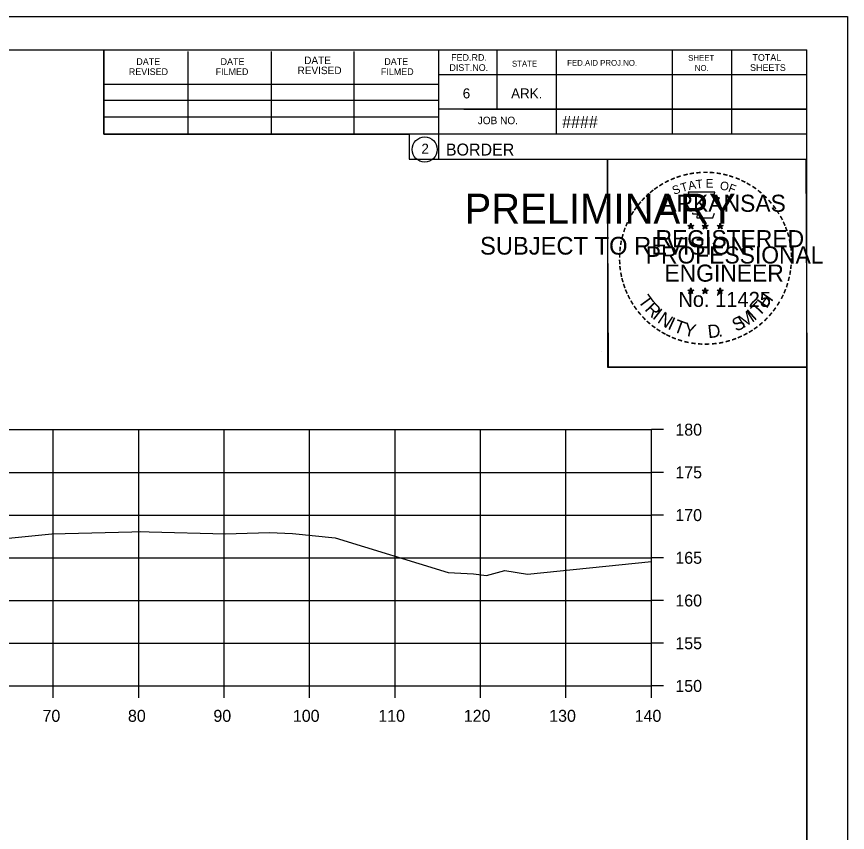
# Model space of a CAD drawing. Extents: x 1368503 to 1373085, y 379840 to 381833.
# Drawn here: x 1372987.8 to 1373085, y 380932.8 to 381028.3 of the extents above; entities that cross this region are included whole.
import ezdxf

# ---------------------------------------------------------------- set-up
doc = ezdxf.new("R2010")
doc.units = 0
for name, color, linetype in [('S_BRIDGE', 7, 'Continuous'), ('S_EDGE_PAVEMENT', 7, 'Continuous'), ('S_LANDSCAPING', 7, 'Continuous'), ('S_MISC_BOUNDARY', 7, 'Continuous'), ('S_MISC_BOUNDARY_ANNOT', 7, 'Continuous'), ('S_PHOTO_CENTERS', 7, 'Continuous'), ('S_PHOTO_NOTES', 7, 'Continuous'), ('S_TRAILS', 7, 'Continuous')]:
    doc.layers.add(name, color=color, linetype=linetype)

msp = doc.modelspace()

# ---------------------------------------------------------------- linework, layer by layer
at = {"layer": 'S_BRIDGE'}
for p, q in [((1372764.081, 381024.423), (1373080.261, 381024.423)), ((1372998.001, 381014.543), (1372998.001, 381024.423)), ((1373037.161, 381024.423), (1373037.161, 381011.623)), ((1373044.001, 381024.423), (1373044.001, 381017.483)), ((1373050.941, 381024.423), (1373050.941, 381014.543)), ((1373064.521, 381024.423), (1373064.521, 381014.543)), ((1373071.461, 381024.423), (1373071.461, 381014.543)), ((1373080.261, 380818.963), (1373080.261, 381024.423)), ((1373007.861, 381014.543), (1373007.861, 381024.223)), ((1373017.621, 381014.543), (1373017.621, 381024.223)), ((1373027.301, 381014.543), (1373027.301, 381024.223)), ((1373080.261, 381021.483), (1373037.161, 381021.483)), ((1373080.261, 381021.503), (1373080.261, 381021.503)), ((1372998.001, 381020.403), (1373037.161, 381020.403)), ((1372998.001, 381018.543), (1373037.161, 381018.543)), ((1372998.001, 381014.543), (1372998.001, 381016.603)), ((1372998.001, 381016.603), (1373037.161, 381016.603)), ((1373080.261, 381017.483), (1373037.161, 381017.483)), ((1373040.121, 381017.483), (1373080.261, 381017.483)), ((1373080.261, 381014.543), (1372998.001, 381014.543)), ((1373037.161, 381011.623), (1373080.261, 381011.623))]:
    msp.add_line(p, q, dxfattribs=at)
msp.add_circle((1373035.548, 381012.759), 1.467, dxfattribs=at)
at = {"layer": 'S_EDGE_PAVEMENT'}
for p, q in [((1373062.081, 380949.963), (1373062.081, 380979.963)), ((1373063.481, 380979.963), (1373062.081, 380979.963)), ((1373063.481, 380974.963), (1373062.081, 380974.963)), ((1373063.481, 380969.963), (1373062.081, 380969.963)), ((1373063.481, 380964.963), (1373062.081, 380964.963)), ((1373063.481, 380959.963), (1373062.081, 380959.963)), ((1373063.481, 380954.963), (1373062.081, 380954.963)), ((1372782.081, 380949.963), (1373062.081, 380949.963)), ((1372992.081, 380948.563), (1372992.081, 380949.963)), ((1373002.081, 380948.563), (1373002.081, 380949.963)), ((1373012.081, 380948.563), (1373012.081, 380949.963)), ((1373022.081, 380948.563), (1373022.081, 380949.963)), ((1373032.081, 380948.563), (1373032.081, 380949.963)), ((1373042.081, 380948.563), (1373042.081, 380949.963)), ((1373052.081, 380948.563), (1373052.081, 380949.963)), ((1373062.081, 380948.563), (1373062.081, 380949.963)), ((1373063.481, 380949.963), (1373062.081, 380949.963))]:
    msp.add_line(p, q, dxfattribs=at)
at = {"layer": 'S_LANDSCAPING'}
for p, q in [((1373066.695, 381004.132), (1373066.654, 381003.88)), ((1373066.695, 381003.767), (1373066.695, 381004.132)), ((1373066.695, 381004.132), (1373066.744, 381003.882)), ((1373068.365, 381004.132), (1373068.324, 381003.88)), ((1373068.365, 381003.767), (1373068.365, 381004.132)), ((1373068.365, 381004.132), (1373068.414, 381003.882)), ((1373070.129, 381004.12), (1373070.088, 381003.868)), ((1373070.129, 381003.755), (1373070.129, 381004.12)), ((1373070.129, 381004.12), (1373070.178, 381003.87)), ((1373066.346, 381003.878), (1373066.695, 381003.767)), ((1373066.346, 381003.878), (1373066.599, 381003.833)), ((1373066.346, 381003.878), (1373066.583, 381003.756)), ((1373066.479, 381003.47), (1373066.695, 381003.767)), ((1373066.479, 381003.47), (1373066.605, 381003.714)), ((1373066.479, 381003.47), (1373066.693, 381003.687)), ((1373066.908, 381003.47), (1373066.693, 381003.684)), ((1373067.042, 381003.878), (1373066.695, 381003.767)), ((1373066.908, 381003.47), (1373066.695, 381003.767)), ((1373067.042, 381003.878), (1373066.756, 381003.829)), ((1373066.908, 381003.47), (1373066.771, 381003.761)), ((1373067.042, 381003.878), (1373066.838, 381003.776)), ((1373068.016, 381003.878), (1373068.365, 381003.767)), ((1373068.016, 381003.878), (1373068.269, 381003.833)), ((1373068.016, 381003.878), (1373068.253, 381003.756)), ((1373068.149, 381003.47), (1373068.365, 381003.767)), ((1373068.149, 381003.47), (1373068.275, 381003.714)), ((1373068.149, 381003.47), (1373068.363, 381003.687)), ((1373068.578, 381003.47), (1373068.363, 381003.684)), ((1373068.712, 381003.878), (1373068.365, 381003.767)), ((1373068.578, 381003.47), (1373068.365, 381003.767)), ((1373068.712, 381003.878), (1373068.426, 381003.829)), ((1373068.578, 381003.47), (1373068.441, 381003.761)), ((1373068.712, 381003.878), (1373068.508, 381003.776)), ((1373069.78, 381003.866), (1373070.129, 381003.755)), ((1373069.78, 381003.866), (1373070.033, 381003.821)), ((1373069.78, 381003.866), (1373070.017, 381003.744)), ((1373069.913, 381003.458), (1373070.129, 381003.755)), ((1373069.913, 381003.458), (1373070.039, 381003.702)), ((1373069.913, 381003.458), (1373070.127, 381003.675)), ((1373070.342, 381003.458), (1373070.127, 381003.672)), ((1373070.476, 381003.866), (1373070.129, 381003.755)), ((1373070.342, 381003.458), (1373070.129, 381003.755)), ((1373070.476, 381003.866), (1373070.19, 381003.817)), ((1373070.342, 381003.458), (1373070.205, 381003.749)), ((1373070.476, 381003.866), (1373070.272, 381003.764)), ((1373066.342, 380996.305), (1373066.691, 380996.194)), ((1373066.342, 380996.305), (1373066.595, 380996.26)), ((1373066.342, 380996.305), (1373066.579, 380996.183)), ((1373066.475, 380995.897), (1373066.691, 380996.194)), ((1373066.475, 380995.897), (1373066.601, 380996.141)), ((1373066.691, 380996.559), (1373066.65, 380996.307)), ((1373066.691, 380996.194), (1373066.691, 380996.559)), ((1373066.691, 380996.559), (1373066.74, 380996.309)), ((1373067.038, 380996.305), (1373066.691, 380996.194)), ((1373066.904, 380995.897), (1373066.691, 380996.194)), ((1373067.038, 380996.305), (1373066.752, 380996.256)), ((1373066.904, 380995.897), (1373066.767, 380996.188)), ((1373067.038, 380996.305), (1373066.834, 380996.203)), ((1373068.011, 380996.305), (1373068.36, 380996.194)), ((1373068.011, 380996.305), (1373068.264, 380996.26)), ((1373068.011, 380996.305), (1373068.248, 380996.183)), ((1373068.144, 380995.897), (1373068.36, 380996.194)), ((1373068.144, 380995.897), (1373068.27, 380996.141)), ((1373068.36, 380996.559), (1373068.319, 380996.307)), ((1373068.36, 380996.194), (1373068.36, 380996.559)), ((1373068.36, 380996.559), (1373068.409, 380996.309)), ((1373068.707, 380996.305), (1373068.36, 380996.194)), ((1373068.573, 380995.897), (1373068.36, 380996.194)), ((1373068.707, 380996.305), (1373068.421, 380996.256)), ((1373068.573, 380995.897), (1373068.436, 380996.188)), ((1373068.707, 380996.305), (1373068.503, 380996.203)), ((1373069.778, 380996.295), (1373070.127, 380996.184)), ((1373069.778, 380996.295), (1373070.031, 380996.25)), ((1373069.778, 380996.295), (1373070.015, 380996.173)), ((1373069.911, 380995.887), (1373070.127, 380996.184)), ((1373069.911, 380995.887), (1373070.037, 380996.131)), ((1373070.127, 380996.549), (1373070.086, 380996.297)), ((1373070.127, 380996.184), (1373070.127, 380996.549)), ((1373070.127, 380996.549), (1373070.176, 380996.299)), ((1373070.474, 380996.295), (1373070.127, 380996.184)), ((1373070.34, 380995.887), (1373070.127, 380996.184)), ((1373070.474, 380996.295), (1373070.188, 380996.246)), ((1373070.34, 380995.887), (1373070.203, 380996.178)), ((1373070.474, 380996.295), (1373070.27, 380996.193)), ((1373066.475, 380995.897), (1373066.689, 380996.114)), ((1373066.904, 380995.897), (1373066.689, 380996.111)), ((1373068.144, 380995.897), (1373068.358, 380996.114)), ((1373068.573, 380995.897), (1373068.358, 380996.111)), ((1373069.911, 380995.887), (1373070.125, 380996.104)), ((1373070.34, 380995.887), (1373070.125, 380996.101))]:
    msp.add_line(p, q, dxfattribs=at)
for points in [[(1373066.387, 381007.756), (1373066.656, 381006.929)], [(1373069.898, 381006.834), (1373070.04, 381007.118), (1373069.355, 381007.094), (1373069.503, 381007.756), (1373066.387, 381007.756)], [(1373066.879, 381005.333), (1373066.879, 381005.246), (1373067.442, 381005.227), (1373067.388, 381004.754), (1373069.258, 381004.754), (1373069.459, 381005.29)], [(1373066.695, 381004.132), (1373066.908, 381003.47), (1373066.346, 381003.878), (1373067.042, 381003.878), (1373066.479, 381003.47), (1373066.695, 381004.132)], [(1373068.365, 381004.132), (1373068.578, 381003.47), (1373068.016, 381003.878), (1373068.712, 381003.878), (1373068.149, 381003.47), (1373068.365, 381004.132)], [(1373070.129, 381004.12), (1373070.342, 381003.458), (1373069.78, 381003.866), (1373070.476, 381003.866), (1373069.913, 381003.458), (1373070.129, 381004.12)], [(1373066.691, 380996.559), (1373066.904, 380995.897), (1373066.342, 380996.305), (1373067.038, 380996.305), (1373066.475, 380995.897), (1373066.691, 380996.559)], [(1373068.36, 380996.559), (1373068.573, 380995.897), (1373068.011, 380996.305), (1373068.707, 380996.305), (1373068.144, 380995.897), (1373068.36, 380996.559)], [(1373070.127, 380996.549), (1373070.34, 380995.887), (1373069.778, 380996.295), (1373070.474, 380996.295), (1373069.911, 380995.887), (1373070.127, 380996.549)]]:
    msp.add_lwpolyline(points, dxfattribs=at)
for centre, radius in [((1373066.694, 381003.766), 0.172), ((1373066.694, 381003.766), 0.145), ((1373068.364, 381003.766), 0.172), ((1373068.364, 381003.766), 0.145), ((1373070.128, 381003.754), 0.172), ((1373066.694, 381003.766), 0.116), ((1373066.694, 381003.766), 0.0991), ((1373066.694, 381003.766), 0.0747), ((1373066.694, 381003.766), 0.0495), ((1373066.694, 381003.766), 0.0296), ((1373068.364, 381003.766), 0.116), ((1373068.364, 381003.766), 0.0991), ((1373068.364, 381003.766), 0.0747), ((1373068.364, 381003.766), 0.0495), ((1373068.364, 381003.766), 0.0296), ((1373070.128, 381003.754), 0.145), ((1373070.128, 381003.754), 0.116), ((1373070.128, 381003.754), 0.0991), ((1373070.128, 381003.754), 0.0747), ((1373070.128, 381003.754), 0.0495), ((1373070.128, 381003.754), 0.0296), ((1373066.69, 380996.193), 0.172), ((1373066.69, 380996.193), 0.145), ((1373066.69, 380996.193), 0.116), ((1373066.69, 380996.193), 0.0991), ((1373066.69, 380996.193), 0.0747), ((1373066.69, 380996.193), 0.0495), ((1373066.69, 380996.193), 0.0296), ((1373068.359, 380996.193), 0.172), ((1373068.359, 380996.193), 0.145), ((1373068.359, 380996.193), 0.116), ((1373068.359, 380996.193), 0.0991), ((1373068.359, 380996.193), 0.0747), ((1373068.359, 380996.193), 0.0495), ((1373068.359, 380996.193), 0.0296), ((1373070.126, 380996.183), 0.172), ((1373070.126, 380996.183), 0.145), ((1373070.126, 380996.183), 0.116), ((1373070.126, 380996.183), 0.0991), ((1373070.126, 380996.183), 0.0747), ((1373070.126, 380996.183), 0.0495), ((1373070.126, 380996.183), 0.0296)]:
    msp.add_circle(centre, radius, dxfattribs=at)
at = {"layer": 'S_MISC_BOUNDARY'}
msp.add_lwpolyline([(1372874.557, 380962.386), (1372926.18, 380962.188), (1372929.874, 380962.189), (1372955.958, 380961.956), (1372968.41, 380961.854), (1372969.229, 380962.173), (1372972.62, 380963.246), (1372983.457, 380966.906), (1372984.077, 380966.974), (1372991.899, 380967.757), (1373001.26, 380968.002), (1373002.326, 380968.027), (1373003.309, 380968.002), (1373012.255, 380967.781), (1373013.501, 380967.805), (1373017.378, 380967.906), (1373020.086, 380967.799), (1373025.072, 380967.294), (1373038.307, 380963.227), (1373041.268, 380963.094), (1373042.787, 380962.899), (1373044.934, 380963.461), (1373047.57, 380963.065), (1373062.081, 380964.517)], dxfattribs=at)
at = {"layer": 'S_PHOTO_CENTERS'}
for p, q in [((1372782.081, 380979.963), (1373062.081, 380979.963)), ((1372782.081, 380979.963), (1373062.081, 380979.963)), ((1372992.081, 380949.963), (1372992.081, 380979.963)), ((1372992.081, 380949.963), (1372992.081, 380979.963)), ((1373002.081, 380949.963), (1373002.081, 380979.963)), ((1373002.081, 380949.963), (1373002.081, 380979.963)), ((1373012.081, 380949.963), (1373012.081, 380979.963)), ((1373012.081, 380949.963), (1373012.081, 380979.963)), ((1373022.081, 380949.963), (1373022.081, 380979.963)), ((1373022.081, 380949.963), (1373022.081, 380979.963)), ((1373032.081, 380949.963), (1373032.081, 380979.963)), ((1373032.081, 380949.963), (1373032.081, 380979.963)), ((1373042.081, 380949.963), (1373042.081, 380979.963)), ((1373042.081, 380949.963), (1373042.081, 380979.963)), ((1373052.081, 380949.963), (1373052.081, 380979.963)), ((1373052.081, 380949.963), (1373052.081, 380979.963)), ((1373062.081, 380949.963), (1373062.081, 380979.963)), ((1373062.081, 380949.963), (1373062.081, 380979.963)), ((1372782.081, 380974.963), (1373062.081, 380974.963)), ((1372782.081, 380974.963), (1373062.081, 380974.963)), ((1372782.081, 380969.963), (1373062.081, 380969.963)), ((1372782.081, 380969.963), (1373062.081, 380969.963)), ((1372782.081, 380964.963), (1373062.081, 380964.963)), ((1372782.081, 380964.963), (1373062.081, 380964.963)), ((1372782.081, 380959.963), (1373062.081, 380959.963)), ((1372782.081, 380959.963), (1373062.081, 380959.963)), ((1372782.081, 380954.963), (1373062.081, 380954.963)), ((1372782.081, 380954.963), (1373062.081, 380954.963)), ((1372782.081, 380949.963), (1373062.081, 380949.963)), ((1372782.081, 380949.963), (1373062.081, 380949.963))]:
    msp.add_line(p, q, dxfattribs=at)
at = {"layer": 'S_PHOTO_NOTES'}
for p, q in [((1372751.681, 381028.318), (1373085.014, 381028.318)), ((1373056.296, 380989.168), (1373056.296, 380989.168))]:
    msp.add_line(p, q, dxfattribs=at)
for points in [[(1372751.674, 381028.318), (1373085.014, 381028.318), (1373085.014, 380814.98), (1372751.674, 380814.98)], [(1372998.001, 381024.423), (1372998.001, 381014.543), (1373033.733, 381014.543), (1373033.733, 381011.623), (1373056.933, 381011.623), (1373056.933, 380987.291), (1373080.261, 380987.291), (1373080.261, 380818.963), (1372764.081, 380818.963), (1372764.081, 381024.423)], [(1373056.933, 381011.623), (1373080.141, 381011.623), (1373080.261, 380987.291), (1373057.054, 380987.291)]]:
    msp.add_lwpolyline(points, close=True, dxfattribs=at)

# ---------------------------------------------------------------- texts
at = {"layer": 'S_BRIDGE'}
for s, height, p in [('DATE', 0.7819, (1373001.801, 381022.663)), ('DATE', 0.7819, (1373011.661, 381022.663)), ('DATE', 0.8792, (1373021.441, 381022.763)), ('DATE', 0.7819, (1373030.821, 381022.663)), ('FED.RD.', 0.7819, (1373038.641, 381023.143)), ('SHEET', 0.684, (1373066.381, 381023.143)), ('TOTAL', 0.7819, (1373073.901, 381023.143)), ('REVISED', 0.8792, (1373020.661, 381021.583)), ('DIST.NO.', 0.7819, (1373038.441, 381021.963)), ('STATE', 0.684, (1373045.761, 381022.463)), ('FED.AID PROJ.NO.', 0.684, (1373052.221, 381022.563)), ('NO.', 0.684, (1373067.161, 381021.963)), ('SHEETS', 0.7819, (1373073.621, 381021.963)), ('REVISED', 0.7819, (1373000.921, 381021.483)), ('FILMED', 0.7819, (1373011.081, 381021.483)), ('FILMED', 0.7819, (1373030.421, 381021.483)), ('6', 1.172, (1373040.001, 381018.743)), ('ARK.', 1.1723, (1373045.661, 381018.743)), ('JOB NO.', 0.8792, (1373041.761, 381015.723)), ('####', 1.4, (1373051.637, 381015.283)), ('2', 1.172, (1373035.165, 381012.273)), ('BORDER', 1.4, (1373038.025, 381012.053))]:
    msp.add_text(s, height=height, rotation=360, dxfattribs=at).set_placement(p)
at = {"layer": 'S_LANDSCAPING'}
for s, height, rotation, p in [('-', 1.6, 19.17608, (1373065.135, 381008.883)), ('-', 1.6, 13.63015, (1373065.885, 381009.124)), ('-', 1.6, 10.21935, (1373066.563, 381009.286)), ('-', 1.6, 5.89682, (1373067.292, 381009.396)), ('-', 1.6, 0.18623, (1373068.064, 381009.468)), ('-', 1.6, 357.74304, (1373068.787, 381009.455)), ('-', 1.6, 352.16172, (1373069.531, 381009.399)), ('-', 1.6, 347.20489, (1373070.25, 381009.285)), ('-', 1.6, 342.3362, (1373070.885, 381009.13)), ('-', 1.6, 34.06357, (1373063.271, 381007.927)), ('-', 1.6, 28.79182, (1373063.868, 381008.297)), ('-', 1.6, 24.30721, (1373064.501, 381008.614)), ('T', 1, 16.4036, (1373065.656, 381007.765)), ('A', 1, 11.21318, (1373066.482, 381008.016)), ('T', 1, 6.02276, (1373067.331, 381008.182)), ('E', 1, 0.83234, (1373068.436, 381008.292)), ('O', 1, 350.4515, (1373070.04, 381008.082)), ('-', 1.6, 337.85509, (1373071.62, 381008.907)), ('-', 1.6, 334.12109, (1373072.251, 381008.636)), ('-', 1.6, 329.64089, (1373072.83, 381008.353)), ('-', 1.6, 38.95066, (1373062.217, 381007.154)), ('-', 1.6, 36.23174, (1373062.693, 381007.532)), ('S', 1, 21.59401, (1373064.742, 381007.434)), ('F', 1, 340.07066, (1373070.994, 381007.854)), ('-', 1.6, 325.86266, (1373073.473, 381007.992)), ('-', 1.6, 320.52971, (1373074.083, 381007.566)), ('-', 1.6, 48.42305, (1373061.336, 381006.259)), ('-', 1.6, 42.96224, (1373061.784, 381006.737)), ('ARKANSAS', 2, 360, (1373063.24, 381005.468)), ('-', 1.6, 315.57859, (1373074.682, 381007.078)), ('-', 1.6, 309.87973, (1373075.251, 381006.528)), ('-', 1.6, 54.23247, (1373060.52, 381005.206)), ('-', 1.6, 50.61417, (1373060.933, 381005.773)), ('-', 1.6, 306.65218, (1373075.776, 381005.926)), ('-', 1.6, 62.87135, (1373059.882, 381004.065)), ('-', 1.6, 58.07063, (1373060.195, 381004.679)), ('-', 1.4, 303.67529, (1373076.262, 381005.358)), ('-', 1.6, 299.66835, (1373076.581, 381004.751)), ('-', 1.6, 67.77427, (1373059.623, 381003.454)), ('-', 1.6, 294.66279, (1373076.905, 381004.139)), ('-', 1.6, 72.39447, (1373059.404, 381002.824)), ('REGISTERED', 2, 360, (1373062.562, 381001.319)), ('DWB', 0.01, 360, (1373066.682, 381003.762)), ('DWB', 0.01, 360, (1373068.352, 381003.762)), ('DWB', 0.01, 360, (1373070.116, 381003.751)), ('-', 1.6, 290.57283, (1373077.162, 381003.562)), ('-', 1.6, 285.12326, (1373077.396, 381002.982)), ('-', 1.6, 81.20126, (1373059.075, 381001.397)), ('-', 1.6, 75.46096, (1373059.207, 381002.11)), ('-', 1.6, 280.54934, (1373077.596, 381002.24)), ('-', 1.6, 85.18634, (1373058.999, 381000.706)), ('PROFESSIONAL', 2, 360, (1373061.414, 380999.415)), ('-', 1.6, 276.59616, (1373077.758, 381001.472)), ('-', 1.6, 89.06224, (1373058.974, 381000.005)), ('-', 1.6, 274.33011, (1373077.818, 381000.75)), ('-', 1.6, 269.94067, (1373077.852, 381000.118)), ('-', 1.6, 94.19588, (1373059.009, 380999.28)), ('-', 1.6, 98.94793, (1373059.081, 380998.613)), ('ENGINEER', 2, 360, (1373063.601, 380997.29)), ('-', 1.6, 263.5172, (1373077.833, 380999.452)), ('-', 1.6, 101.71495, (1373059.216, 380997.88)), ('-', 1.6, 260.99529, (1373077.762, 380998.798)), ('-', 1.6, 105.45785, (1373059.378, 380997.285)), ('-', 1.6, 252.86809, (1373077.471, 380997.4)), ('-', 1.6, 255.7626, (1373077.652, 380998.12)), ('-', 1.6, 109.08742, (1373059.593, 380996.654)), ('-', 1.6, 114.06432, (1373059.847, 380996.058)), ('DWB', 0.01, 360, (1373066.678, 380996.189)), ('DWB', 0.01, 360, (1373068.347, 380996.19)), ('DWB', 0.01, 360, (1373070.114, 380996.18)), ('-', 1.6, 247.88866, (1373077.248, 380996.727)), ('-', 1.6, 115.72885, (1373060.152, 380995.44)), ('T', 1.54, 306.04056, (1373060.451, 380995.032)), ('No. 11425', 1.757, 360, (1373065.229, 380994.339)), ('H', 1.54, 54.60883, (1373075.571, 380994.068)), ('-', 1.6, 244.61971, (1373076.986, 380996.098)), ('-', 1.6, 120.44712, (1373060.509, 380994.854)), ('-', 1.6, 125.89344, (1373060.912, 380994.293)), ('R', 1.54, 314.00497, (1373061.213, 380993.985)), ('T', 1.54, 46.64442, (1373074.681, 380993.125)), ('-', 1.6, 233.84524, (1373076.19, 380994.693)), ('-', 1.6, 239.07125, (1373076.592, 380995.346)), ('-', 1.6, 130.71812, (1373061.374, 380993.741)), ('-', 1.6, 134.22381, (1373061.891, 380993.196)), ('I', 1.54, 321.96938, (1373062.114, 380993.053)), ('N', 1.54, 326.50021, (1373062.681, 380992.581)), ('S', 1.54, 26.9312, (1373071.997, 380991.394)), ('M', 1.54, 32.65632, (1373072.836, 380991.8)), ('I', 1.54, 42.11359, (1373074.12, 380992.647)), ('-', 1.6, 231.25377, (1373075.76, 380994.127)), ('-', 1.6, 138.93382, (1373062.416, 380992.732)), ('-', 1.6, 144.64634, (1373062.972, 380992.326)), ('I', 1.54, 335.36034, (1373063.889, 380991.795)), ('T', 1.54, 339.89117, (1373064.55, 380991.468)), ('Y', 1.54, 347.85558, (1373065.767, 380991.022)), ('D', 1.54, 6.39691, (1373068.752, 380990.664)), ('-', 1.6, 221.08509, (1373074.759, 380993.054)), ('-', 1.6, 225.76533, (1373075.281, 380993.563)), ('-', 1.6, 148.08978, (1373063.533, 380991.955)), ('-', 1.6, 151.57039, (1373064.112, 380991.63)), ('-', 1.6, 207.35684, (1373073.118, 380991.849)), ('-', 1.6, 212.24909, (1373073.676, 380992.195)), ('-', 1.6, 215.73633, (1373074.21, 380992.582)), ('-', 1.6, 154.60019, (1373064.634, 380991.383)), ('-', 1.6, 158.56121, (1373065.258, 380991.129)), ('-', 1.6, 162.79826, (1373065.945, 380990.916)), ('-', 1.6, 167.55551, (1373066.66, 380990.752)), ('.', 1.54, 13.76417, (1373069.944, 380990.791)), ('-', 1.6, 195.47429, (1373071.198, 380991.015)), ('-', 1.6, 200.71842, (1373071.875, 380991.257)), ('-', 1.6, 204.25161, (1373072.494, 380991.53)), ('-', 1.6, 173.11546, (1373067.432, 380990.642)), ('-', 1.6, 176.51827, (1373068.18, 380990.589)), ('-', 1.6, 181.59176, (1373068.924, 380990.608)), ('-', 1.6, 185.81666, (1373069.733, 380990.684)), ('-', 1.6, 191.28576, (1373070.469, 380990.816))]:
    msp.add_text(s, height=height, rotation=rotation, dxfattribs=at).set_placement(p)
at = {"layer": 'S_MISC_BOUNDARY_ANNOT'}
for s, height, p in [('PRELIMINARY', 3.5, (1373040.212, 381004.086)), ('DWB', 0.01, (1373040.959, 381005.935)), ('SUBJECT TO REVISION', 2.07511, (1373042.021, 381000.457))]:
    msp.add_text(s, height=height, rotation=360, dxfattribs=at).set_placement(p)
at = {"layer": 'S_TRAILS'}
for s, p in [('180', (1373064.881, 380979.263)), ('175', (1373064.881, 380974.263)), ('170', (1373064.881, 380969.263)), ('165', (1373064.881, 380964.263)), ('160', (1373064.881, 380959.263)), ('155', (1373064.881, 380954.263)), ('150', (1373064.881, 380949.263)), ('70', (1372990.82, 380945.763)), ('80', (1373000.82, 380945.763)), ('90', (1373010.82, 380945.763)), ('100', (1373020.12, 380945.763)), ('110', (1373030.12, 380945.763)), ('120', (1373040.12, 380945.763)), ('130', (1373050.12, 380945.763)), ('140', (1373060.12, 380945.763))]:
    msp.add_text(s, height=1.4, dxfattribs=at).set_placement(p)

doc.saveas('drawing.dxf')
